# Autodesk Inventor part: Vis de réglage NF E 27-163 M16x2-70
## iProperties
Shininess: 64.0
Length Units: 11269
Angle Units: 11279
Time Units: 11290
Mass Units: 11283
Length Display Precision: 3
Angle Display Precision: 2
Compacted: True
Part Number: Vis de réglage NF E 27-163 M16x2-70
Document SubType Name: Modeling
Created: 2005-02
Material: Par défaut
Designer: LEGERET Philippe
Catalog Web Link: www.traceparts.com
Description: Vis de réglage M16x2-70 6.8 - NF E 27-163
Density: 0.0
Volumn: 0.0
Area: 0.0
PropertySet Name: Model Information
Control State: 0
Master: False
Checked Out: False
Author: Trace Parts S.A.
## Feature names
1. Base1
